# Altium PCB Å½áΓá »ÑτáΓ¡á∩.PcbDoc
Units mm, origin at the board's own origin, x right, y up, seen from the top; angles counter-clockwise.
Board outline 31.5 x 30.25 mm, 4 copper layers (Top Layer, +5 ?, GND, Bottom Layer), stack 0.911 mm thick; 8 components, 10 nets, 26 pads, 0 vias.
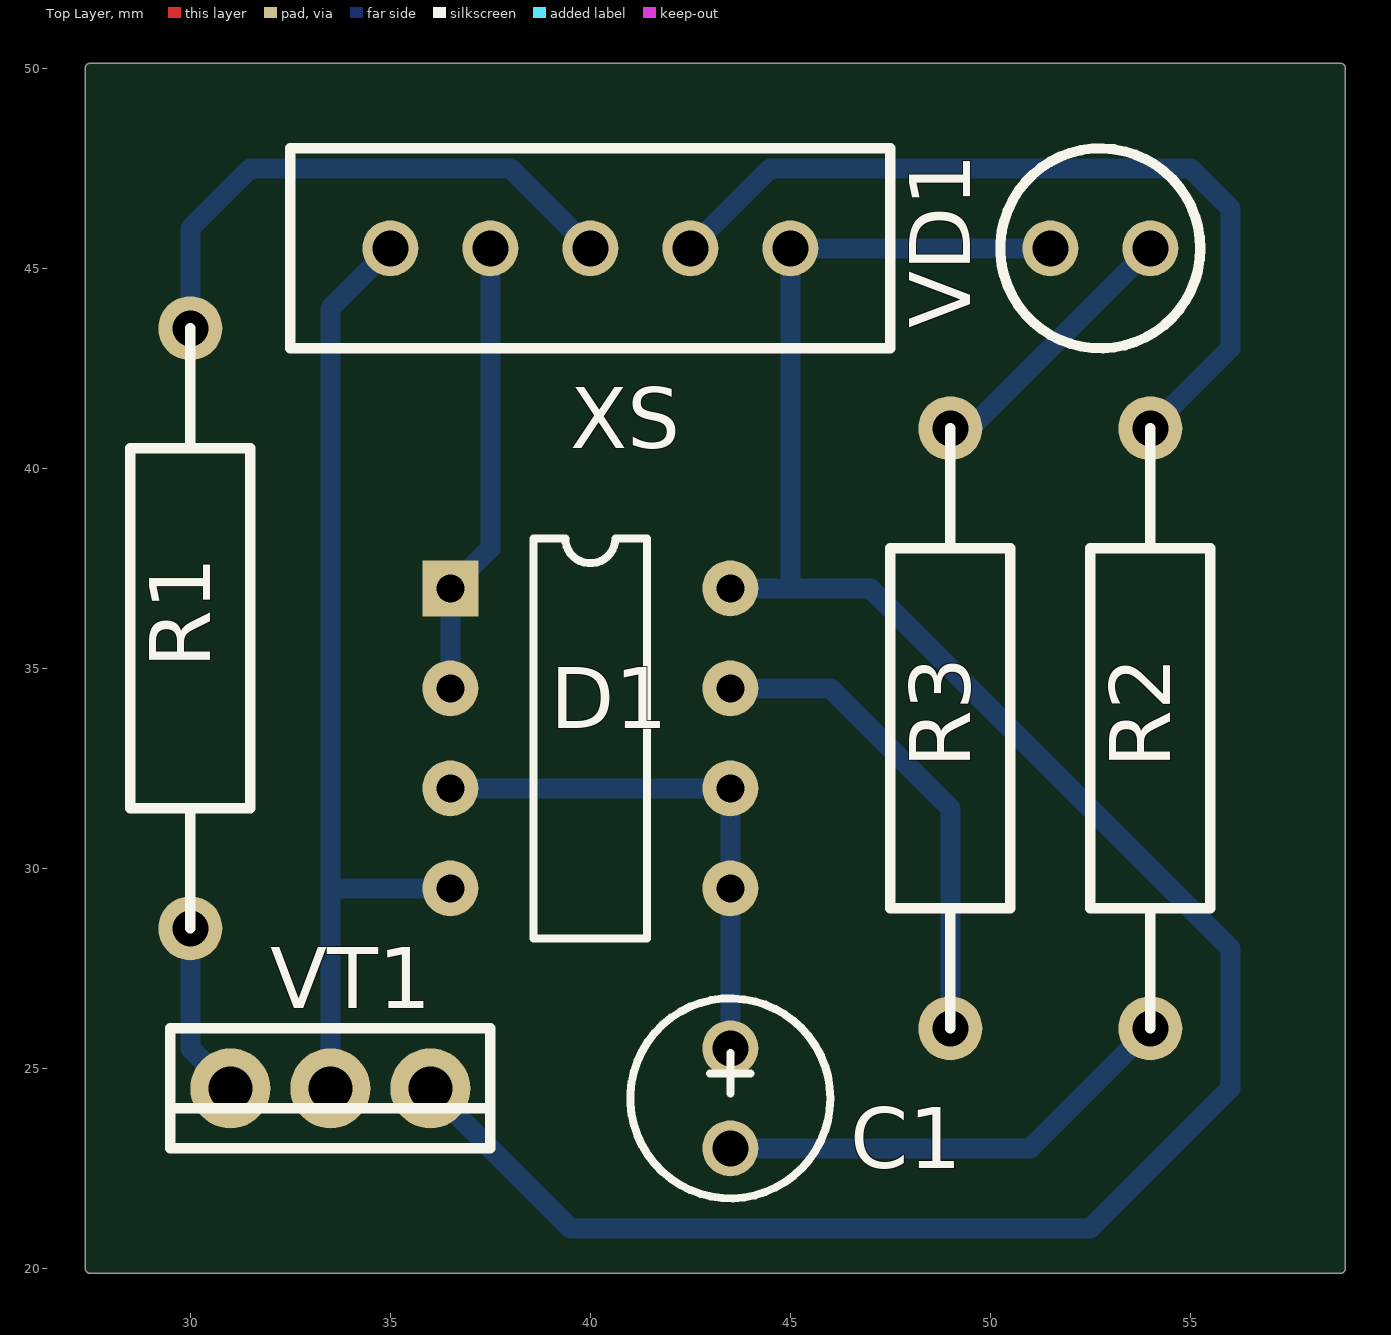
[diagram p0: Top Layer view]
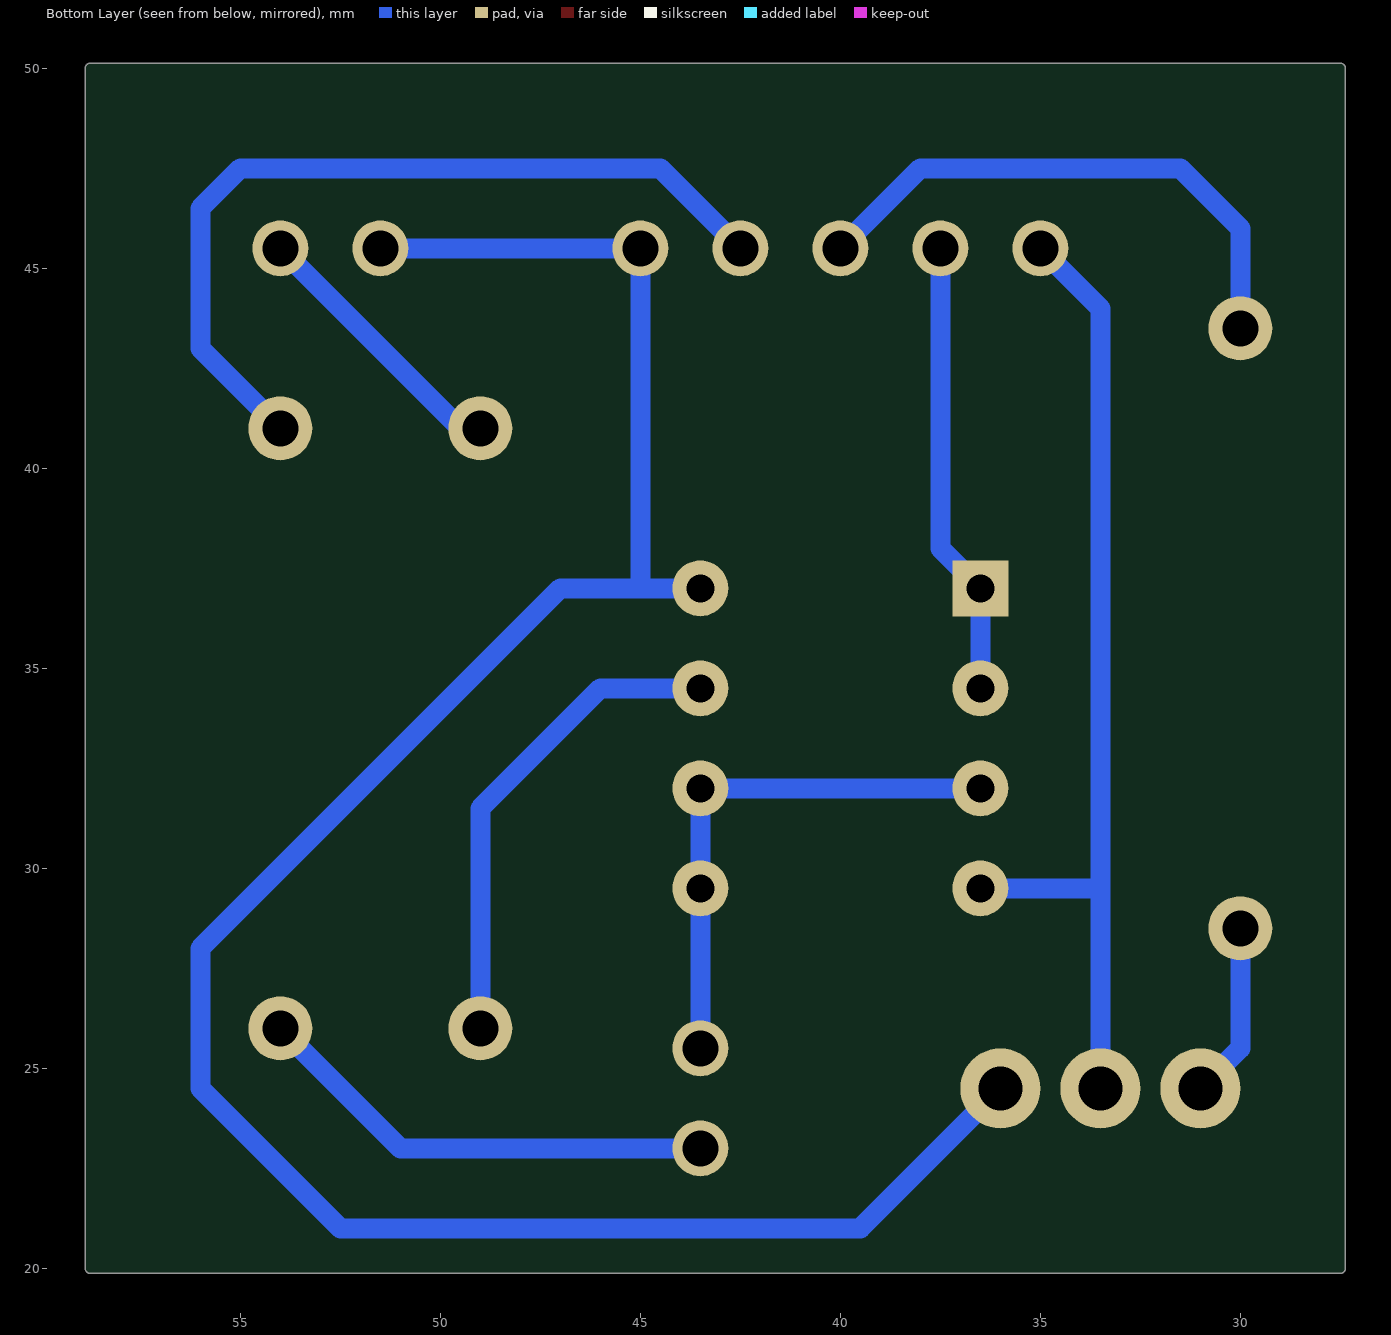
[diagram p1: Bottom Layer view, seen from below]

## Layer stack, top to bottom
Top Solder: solder mask 0.03, Solder Resist, Dk 3.5
Top Layer: signal copper 0.0356
Dielectric1: prepreg 0.13, 2x1080, Dk 4.5
+5 ?: signal copper 0.035
Dielectric2: core 0.51, FR-4, Dk 4.5
GND: signal copper 0.035
Dielectric3: prepreg 0.13, 2x1080, Dk 4.5
Bottom Layer: signal copper 0.035
Bottom Solder: solder mask 0.03, Solder Resist, Dk 3.5

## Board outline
27.373,20 ccw(c27.5,20) 27.5,19.873 58.75,19.873 ccw(c58.75,20) 58.877,20 58.877,50 ccw(c58.75,50) 58.75,50.127 27.5,50.127 ccw(c27.5,50) 27.373,50

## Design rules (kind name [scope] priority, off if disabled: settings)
Clearance [All] p1: gap=0.15
PasteMaskExpansion [All] p1: expansion=0.05
PlaneClearance [All] p1: clearance=0.6
PlaneConnect [All] p1: planeconnectstyle=Relief reliefexpansion=0.6 reliefentries=4 reliefconductorwidth=0.25 reliefairgap=0.3
PolygonConnect [All] p1: connectstyle=Relief reliefconductorwidth=0.25 reliefentries=4 polygonreliefangle="90 Angle" airgapwidth=0.25
RoutingCorners [All] p1: cornerstyle=45-Degree minsetback=3 maxsetback=3
RoutingLayers [All] p1: top layer_v5=TRUE mid layer 1_v5=FALSE mid layer 2_v5=FALSE bottom layer_v5=TRUE
RoutingVias [All] p1: holewidth=0.6 width=1.2 viastyle="Through Hole" minholewidth=0.6 minwidth=1.2 maxholewidth=0.6 maxwidth=1.2
SMDToCorner [All] p1: distance=393701
SMDToPlane [All] p1: distance=393701
SolderMaskExpansion [All] p1: expansion=0.1
Width [All] p1: maxlimit=0.5 minlimit=0.15 preferedwidth=0.5
24 further rules are at their usual default settings.

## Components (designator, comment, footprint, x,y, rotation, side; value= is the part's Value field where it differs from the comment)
C1 "Конденсатор" "для электролитич.конденсатора" 43.5,23 r90 top (schematic designator С1)
D1 "Микросхема" DIP8 36.5,37 r0 top
R1 "резистор" "ПМ для резистора" 30,28.5 r90 top
R2 "резистор" "ПМ для резистора" 54,26 r90 top
R3 "резистор" "ПМ для резистора" 49,26 r90 top
VD1 "Светодиод" "для светоиода" 54,45.5 r180 top
VT1 "КТ315" "ПМ для кт 315" 36,24.5 r180 top
? "Соединитель" "для соединителя" 35,45.5 r90 top

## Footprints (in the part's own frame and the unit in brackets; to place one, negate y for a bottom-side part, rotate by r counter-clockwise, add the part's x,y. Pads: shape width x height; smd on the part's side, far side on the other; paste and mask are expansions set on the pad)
DIP8 [mm]
  rect 1.4x1.4 hole 0.7: 1(0,0)
  round 1.4 hole 0.7: 2(0,-2.5) 3(0,-5) 4(0,-7.5) 5(7,-7.5) 6(7,-5) 7(7,-2.5) 8(7,0)
  silkscreen extent 2.08,-8.75 4.91,1.25
"для светоиода" [mm]
  round 1.4 hole 0.9: A(0,0) K(2.5,0)
  silkscreen extent -1.25,-2.5 3.75,2.5
"для соединителя" [mm]
  round 1.4 hole 0.9: 1(0,0) 2(0,-2.5) 3(0,-5) 4(0,-7.5) 5(0,-10)
  silkscreen extent -2.5,-12.5 2.5,2.5
"для электролитич.конденсатора" [mm]
  round 1.4 hole 0.9: 1(0,0) 2(2.5,0)
  silkscreen extent -1.25,-2.5 3.75,2.5
"ПМ для кт 315" [mm]
  round 2 hole 1.1: B(5,0) C(2.5,0) E(0,0)
  silkscreen extent -1.5,-1.5 6.5,1.5
"ПМ для резистора" [mm]
  round 1.6 hole 0.9: 1(0,0) 2(15,0)
  silkscreen extent 0,-1.5 15,1.5

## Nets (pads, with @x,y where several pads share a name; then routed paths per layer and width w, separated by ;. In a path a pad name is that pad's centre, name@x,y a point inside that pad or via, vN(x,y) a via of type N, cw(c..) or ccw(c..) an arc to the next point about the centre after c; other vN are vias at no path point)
Net_1: ?.1 D1.4 VT1.C | length 24.6
  Bottom Layer w0.5: VT1.C 33.5,29.5 ; ?.1 33.5,44 33.5,29.5 ; D1.4 33.5,29.5
Net_2: ?.2 D1.1 D1.2 | length 11.4
  Bottom Layer w0.5: D1.2 D1.1 37.5,38 ?.2
Net_3: ?.3 R1.2 | length 13.9
  Bottom Layer w0.5: R1.2 30,46 31.5,47.5 38,47.5 ?.3
Net_4: ?.4 R2.2 | length 21.1
  Bottom Layer w0.5: ?.4 44.5,47.5 55,47.5 56,46.5 56,43 R2.2
Net_5: ?.5 D1.8 VD1.K VT1.E | length 57.6
  Bottom Layer w0.5: VT1.E 39.5,21 52.5,21 56,24.5 56,28 47,37 45,37 ; D1.8 45,37 ; VD1.K ?.5 45,37
NetD1_3: C1.2 D1.3 D1.5 D1.6 | length 13.5
  Bottom Layer w0.5: D1.3 D1.6 D1.5 C1.2
NetD1_7: D1.7 R3.1 | length 12.2
  Bottom Layer w0.5: D1.7 46,34.5 49,31.5 R3.1
NetR1_1: R1.1 VT1.B | length 4.4
  Bottom Layer w0.5: R1.1 30,25.5 VT1.B
NetR2_1: C1.1 R2.1 | length 11.7
  Bottom Layer w0.5: C1.1 51,23 R2.1
NetR3_2: R3.2 VD1.A | length 6.9
  Bottom Layer w0.15: R3.2 R3.2@49.5,41
  Bottom Layer w0.5: R3.2@49.5,41 VD1.A

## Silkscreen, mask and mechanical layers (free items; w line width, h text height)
Top Overlay:
  text "XS" at 39.5,40.5 h1.52
Mechanical 1:
  lines w0.254: 27.5,20 58.75,20 58.75,50 27.5,50 27.5,20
